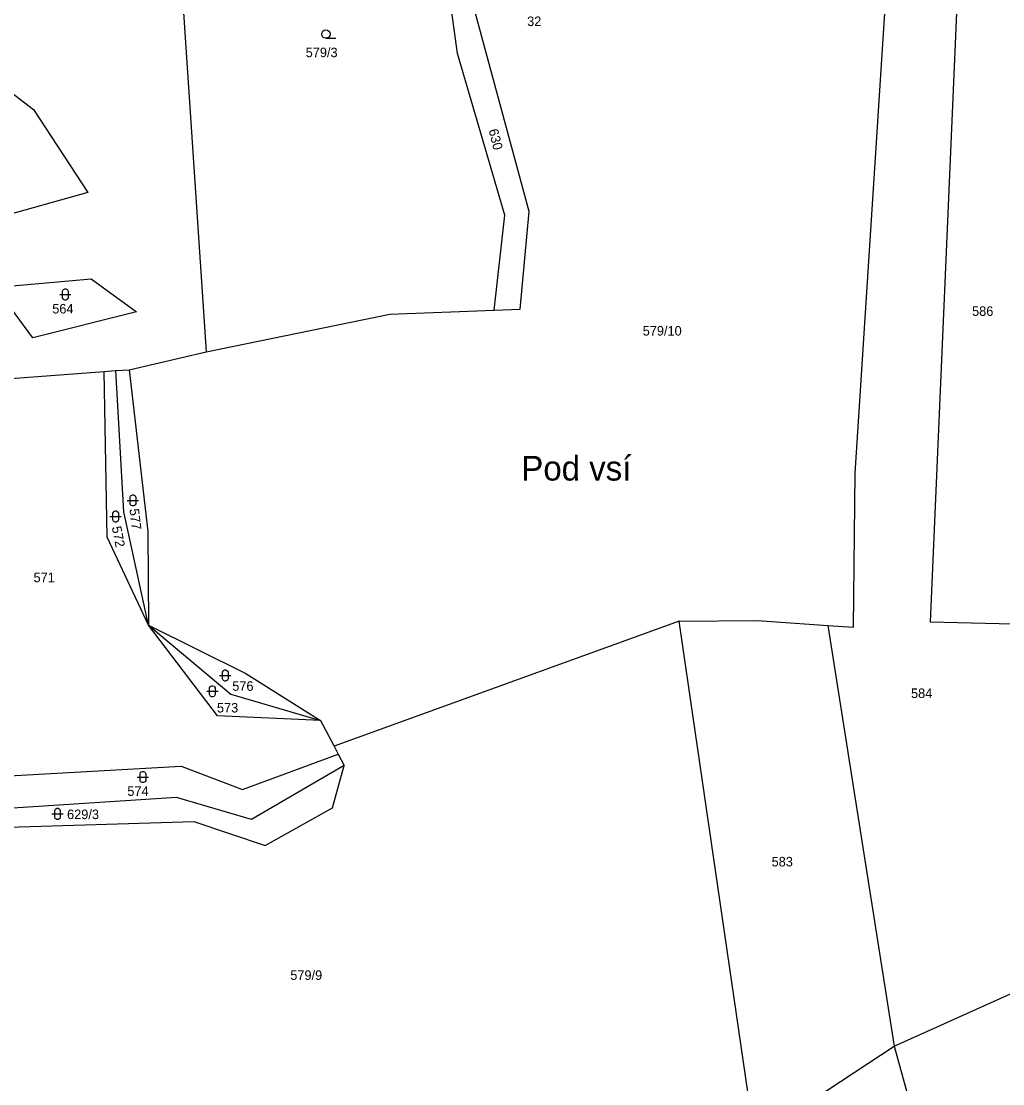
# Model space of a CAD drawing. Extents: x -794421 to -792735, y -1117671 to -1115559.
# Drawn here: x -793541.7 to -793366.7, y -1117244.8 to -1117055.3 of the extents above; entities that cross this region are included whole.
import ezdxf

# ---------------------------------------------------------------- set-up
doc = ezdxf.new("R2010")
doc.units = 0
for name, color, linetype in [('Vrstva 1', 7, 'Continuous'), ('Vrstva 14', 7, 'Continuous'), ('Vrstva 16', 7, 'Continuous'), ('Vrstva 23', 7, 'Continuous'), ('Vrstva 39', 7, 'Continuous')]:
    doc.layers.add(name, color=color, linetype=linetype)

msp = doc.modelspace()

# ---------------------------------------------------------------- linework, layer by layer
at = {"layer": 'Vrstva 1'}
for p, q in [((-793515.34, -1117015.21), (-793508.73, -1117114.25)), ((-793392.98, -1117135.89), (-793387.04, -1117043.8)), ((-793374.49, -1117043.45), (-793379.6, -1117162.41)), ((-793463.93, -1117061.05), (-793465.13, -1117052.35)), ((-793451.13, -1117089.23), (-793460.94, -1117053)), ((-793556.73, -1117057.87), (-793539.56, -1117071.02)), ((-793455.5, -1117089.87), (-793463.93, -1117061.05)), ((-793539.56, -1117071.02), (-793529.85, -1117085.83)), ((-793529.85, -1117085.83), (-793551.48, -1117091.9)), ((-793452.73, -1117106.64), (-793451.13, -1117089.23)), ((-793457.39, -1117106.82), (-793455.5, -1117089.87)), ((-793546.3, -1117102.76), (-793529.27, -1117101.25)), ((-793539.64, -1117111.76), (-793546.3, -1117102.76)), ((-793529.27, -1117101.25), (-793521.15, -1117107.14)), ((-793475.98, -1117107.52), (-793457.39, -1117106.82)), ((-793457.39, -1117106.82), (-793452.73, -1117106.64)), ((-793521.15, -1117107.14), (-793539.64, -1117111.76)), ((-793508.73, -1117114.25), (-793475.98, -1117107.52)), ((-793522.48, -1117117.43), (-793508.73, -1117114.25)), ((-793558.5, -1117120.1), (-793526.93, -1117117.73)), ((-793526.93, -1117117.73), (-793524.87, -1117117.59)), ((-793526.43, -1117147.27), (-793526.93, -1117117.73)), ((-793524.87, -1117117.59), (-793522.48, -1117117.43)), ((-793523.41, -1117142.77), (-793524.87, -1117117.59)), ((-793522.48, -1117117.43), (-793519.16, -1117146.31)), ((-793393.31, -1117163.32), (-793392.98, -1117135.89)), ((-793519.01, -1117162.99), (-793523.41, -1117142.77)), ((-793519.16, -1117146.31), (-793519.01, -1117162.99)), ((-793519.01, -1117162.99), (-793526.43, -1117147.27)), ((-793519.01, -1117162.99), (-793504.37, -1117175.28)), ((-793506.73, -1117179.15), (-793519.01, -1117162.99)), ((-793519.01, -1117162.99), (-793501.66, -1117171.6)), ((-793424.39, -1117162.26), (-793485.93, -1117184.59)), ((-793424.39, -1117162.26), (-793410.44, -1117162.13)), ((-793410.91, -1117254.36), (-793424.39, -1117162.26)), ((-793410.44, -1117162.13), (-793397.88, -1117163.06)), ((-793397.88, -1117163.06), (-793386.06, -1117238.09)), ((-793397.88, -1117163.06), (-793393.31, -1117163.32)), ((-793379.6, -1117162.41), (-793364.89, -1117162.78)), ((-793501.66, -1117171.6), (-793488.33, -1117180)), ((-793504.37, -1117175.28), (-793488.33, -1117180)), ((-793488.33, -1117180), (-793506.73, -1117179.15)), ((-793488.33, -1117180), (-793485.93, -1117184.59)), ((-793502.28, -1117192.32), (-793485.21, -1117185.97)), ((-793485.93, -1117184.59), (-793485.21, -1117185.97)), ((-793485.21, -1117185.97), (-793484.12, -1117188.04)), ((-793550.39, -1117190.25), (-793513.18, -1117188.14)), ((-793513.18, -1117188.14), (-793502.28, -1117192.32)), ((-793484.12, -1117188.04), (-793500.63, -1117197.64)), ((-793486.19, -1117195.58), (-793484.12, -1117188.04)), ((-793514.05, -1117193.72), (-793550.31, -1117196.07)), ((-793500.63, -1117197.64), (-793514.05, -1117193.72)), ((-793498.23, -1117202.29), (-793486.19, -1117195.58)), ((-793565.83, -1117199.7), (-793510.97, -1117198.02)), ((-793510.97, -1117198.02), (-793498.23, -1117202.29)), ((-793386.06, -1117238.09), (-793361.44, -1117226.97)), ((-793410.91, -1117254.36), (-793386.06, -1117238.09)), ((-793386.06, -1117238.09), (-793375.69, -1117275.37))]:
    msp.add_line(p, q, dxfattribs=at)
at = {"layer": 'Vrstva 23'}
for p, q in [((-793487.39, -1117058.34), (-793485.64, -1117058.34)), ((-793534.16, -1117103.12), (-793533.96, -1117103.02)), ((-793533.96, -1117103.02), (-793533.76, -1117103.02)), ((-793533.76, -1117103.02), (-793533.56, -1117103.12)), ((-793534.86, -1117104.02), (-793532.86, -1117104.02)), ((-793534.36, -1117103.42), (-793534.26, -1117103.22)), ((-793534.36, -1117104.62), (-793534.36, -1117103.42)), ((-793534.26, -1117104.82), (-793534.36, -1117104.62)), ((-793534.26, -1117103.22), (-793534.16, -1117103.12)), ((-793534.16, -1117104.92), (-793534.26, -1117104.82)), ((-793533.96, -1117105.02), (-793534.16, -1117104.92)), ((-793533.56, -1117104.92), (-793533.76, -1117105.02)), ((-793533.56, -1117103.12), (-793533.46, -1117103.22)), ((-793533.46, -1117104.82), (-793533.56, -1117104.92)), ((-793533.46, -1117103.22), (-793533.36, -1117103.42)), ((-793533.36, -1117104.62), (-793533.46, -1117104.82)), ((-793533.36, -1117103.42), (-793533.36, -1117104.62)), ((-793533.76, -1117105.02), (-793533.96, -1117105.02)), ((-793522.81, -1117140.74), (-793520.81, -1117140.74)), ((-793522.31, -1117140.14), (-793522.21, -1117139.94)), ((-793522.31, -1117141.34), (-793522.31, -1117140.14)), ((-793522.21, -1117139.94), (-793522.11, -1117139.84)), ((-793522.11, -1117139.84), (-793521.91, -1117139.74)), ((-793521.91, -1117139.74), (-793521.71, -1117139.74)), ((-793521.71, -1117139.74), (-793521.51, -1117139.84)), ((-793521.51, -1117139.84), (-793521.41, -1117139.94)), ((-793521.41, -1117139.94), (-793521.31, -1117140.14)), ((-793521.31, -1117140.14), (-793521.31, -1117141.34)), ((-793525.4, -1117143.02), (-793525.3, -1117142.82)), ((-793525.3, -1117142.82), (-793525.2, -1117142.72)), ((-793525.2, -1117142.72), (-793525, -1117142.62)), ((-793525, -1117142.62), (-793524.8, -1117142.62)), ((-793524.8, -1117142.62), (-793524.6, -1117142.72)), ((-793524.6, -1117142.72), (-793524.5, -1117142.82)), ((-793524.5, -1117142.82), (-793524.4, -1117143.02)), ((-793522.21, -1117141.54), (-793522.31, -1117141.34)), ((-793522.11, -1117141.64), (-793522.21, -1117141.54)), ((-793521.91, -1117141.74), (-793522.11, -1117141.64)), ((-793521.71, -1117141.74), (-793521.91, -1117141.74)), ((-793521.51, -1117141.64), (-793521.71, -1117141.74)), ((-793521.41, -1117141.54), (-793521.51, -1117141.64)), ((-793521.31, -1117141.34), (-793521.41, -1117141.54)), ((-793525.9, -1117143.62), (-793523.9, -1117143.62)), ((-793525.4, -1117144.22), (-793525.4, -1117143.02)), ((-793525.3, -1117144.42), (-793525.4, -1117144.22)), ((-793525.2, -1117144.52), (-793525.3, -1117144.42)), ((-793525, -1117144.62), (-793525.2, -1117144.52)), ((-793524.8, -1117144.62), (-793525, -1117144.62)), ((-793524.6, -1117144.52), (-793524.8, -1117144.62)), ((-793524.5, -1117144.42), (-793524.6, -1117144.52)), ((-793524.4, -1117144.22), (-793524.5, -1117144.42)), ((-793524.4, -1117143.02), (-793524.4, -1117144.22)), ((-793505.84, -1117171.38), (-793505.74, -1117171.18)), ((-793505.74, -1117171.18), (-793505.64, -1117171.08)), ((-793505.64, -1117171.08), (-793505.44, -1117170.98)), ((-793505.44, -1117170.98), (-793505.24, -1117170.98)), ((-793505.24, -1117170.98), (-793505.04, -1117171.08)), ((-793505.04, -1117171.08), (-793504.94, -1117171.18)), ((-793504.94, -1117171.18), (-793504.84, -1117171.38)), ((-793506.34, -1117171.98), (-793504.34, -1117171.98)), ((-793505.84, -1117172.58), (-793505.84, -1117171.38)), ((-793505.74, -1117172.78), (-793505.84, -1117172.58)), ((-793505.64, -1117172.88), (-793505.74, -1117172.78)), ((-793505.44, -1117172.98), (-793505.64, -1117172.88)), ((-793505.24, -1117172.98), (-793505.44, -1117172.98)), ((-793505.04, -1117172.88), (-793505.24, -1117172.98)), ((-793504.94, -1117172.78), (-793505.04, -1117172.88)), ((-793504.84, -1117172.58), (-793504.94, -1117172.78)), ((-793504.84, -1117171.38), (-793504.84, -1117172.58)), ((-793508.63, -1117174.78), (-793506.63, -1117174.78)), ((-793508.13, -1117174.18), (-793508.03, -1117173.98)), ((-793508.13, -1117175.38), (-793508.13, -1117174.18)), ((-793508.03, -1117173.98), (-793507.93, -1117173.88)), ((-793507.93, -1117173.88), (-793507.73, -1117173.78)), ((-793507.73, -1117173.78), (-793507.53, -1117173.78)), ((-793507.53, -1117173.78), (-793507.33, -1117173.88)), ((-793507.33, -1117173.88), (-793507.23, -1117173.98)), ((-793507.23, -1117173.98), (-793507.13, -1117174.18)), ((-793507.13, -1117174.18), (-793507.13, -1117175.38)), ((-793508.03, -1117175.58), (-793508.13, -1117175.38)), ((-793507.93, -1117175.68), (-793508.03, -1117175.58)), ((-793507.73, -1117175.78), (-793507.93, -1117175.68)), ((-793507.53, -1117175.78), (-793507.73, -1117175.78)), ((-793507.33, -1117175.68), (-793507.53, -1117175.78)), ((-793507.23, -1117175.58), (-793507.33, -1117175.68)), ((-793507.13, -1117175.38), (-793507.23, -1117175.58)), ((-793521.03, -1117190.07), (-793519.03, -1117190.07)), ((-793520.53, -1117189.47), (-793520.43, -1117189.27)), ((-793520.53, -1117190.67), (-793520.53, -1117189.47)), ((-793520.43, -1117189.27), (-793520.33, -1117189.17)), ((-793520.33, -1117189.17), (-793520.13, -1117189.07)), ((-793520.13, -1117189.07), (-793519.93, -1117189.07)), ((-793519.93, -1117189.07), (-793519.73, -1117189.17)), ((-793519.73, -1117189.17), (-793519.63, -1117189.27)), ((-793519.63, -1117189.27), (-793519.53, -1117189.47)), ((-793519.53, -1117189.47), (-793519.53, -1117190.67)), ((-793520.43, -1117190.87), (-793520.53, -1117190.67)), ((-793520.33, -1117190.97), (-793520.43, -1117190.87)), ((-793520.13, -1117191.07), (-793520.33, -1117190.97)), ((-793519.93, -1117191.07), (-793520.13, -1117191.07)), ((-793519.73, -1117190.97), (-793519.93, -1117191.07)), ((-793519.63, -1117190.87), (-793519.73, -1117190.97)), ((-793519.53, -1117190.67), (-793519.63, -1117190.87)), ((-793535.76, -1117196.05), (-793535.66, -1117195.85)), ((-793535.66, -1117195.85), (-793535.56, -1117195.75)), ((-793535.56, -1117195.75), (-793535.36, -1117195.65)), ((-793535.36, -1117195.65), (-793535.16, -1117195.65)), ((-793535.16, -1117195.65), (-793534.96, -1117195.75)), ((-793534.96, -1117195.75), (-793534.86, -1117195.85)), ((-793534.86, -1117195.85), (-793534.76, -1117196.05)), ((-793536.26, -1117196.65), (-793534.26, -1117196.65)), ((-793535.76, -1117197.25), (-793535.76, -1117196.05)), ((-793535.66, -1117197.45), (-793535.76, -1117197.25)), ((-793535.56, -1117197.55), (-793535.66, -1117197.45)), ((-793535.36, -1117197.65), (-793535.56, -1117197.55)), ((-793535.16, -1117197.65), (-793535.36, -1117197.65)), ((-793534.96, -1117197.55), (-793535.16, -1117197.65)), ((-793534.86, -1117197.45), (-793534.96, -1117197.55)), ((-793534.76, -1117197.25), (-793534.86, -1117197.45)), ((-793534.76, -1117196.05), (-793534.76, -1117197.25))]:
    msp.add_line(p, q, dxfattribs=at)
msp.add_circle((-793487.39, -1117057.59), 0.75, dxfattribs=at)

# ---------------------------------------------------------------- texts
at = {"layer": 'Vrstva 14'}
for s, p in [('579/3', (-793490.993, -1117061.71)), ('564', (-793536.199, -1117107.41)), ('586', (-793372.143, -1117107.84)), ('579/10', (-793430.885, -1117111.35)), ('571', (-793539.533, -1117155.33)), ('576', (-793504.09, -1117174.69)), ('584', (-793383.029, -1117175.98)), ('573', (-793506.82, -1117178.56)), ('574', (-793522.805, -1117193.43)), ('629/3', (-793533.55, -1117197.57)), ('583', (-793407.893, -1117206.01)), ('579/9', (-793493.743, -1117226.24))]:
    msp.add_text(s, height=1.7, dxfattribs=at).set_placement(p)
for s, rotation, p in [('630', 284.22504, (-793458.387, -1117074.721)), ('577', 276.9885, (-793522.433, -1117142.31)), ('572', 281.29383, (-793525.594, -1117145.514))]:
    msp.add_text(s, height=1.7, rotation=rotation, dxfattribs=at).set_placement(p)
at = {"layer": 'Vrstva 16'}
msp.add_text('32', height=1.7, dxfattribs=at).set_placement((-793451.5, -1117056.16))
at = {"layer": 'Vrstva 39'}
msp.add_text('Pod vsí', height=4.4, dxfattribs=at).set_placement((-793452.53, -1117137.2))

doc.saveas('drawing.dxf')
